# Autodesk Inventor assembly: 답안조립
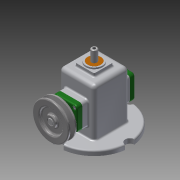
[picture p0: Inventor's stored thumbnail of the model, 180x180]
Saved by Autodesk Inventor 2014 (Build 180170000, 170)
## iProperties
Created: 2018-07
Part Number: 답안조립
Document SubType Name: Assembly
Designer: kh
Author: kh
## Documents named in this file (16)
- C:\Users\kh\Desktop\480707V1019\답안조립.iam
- C:\Users\kh\Desktop\480707V1019\본체.ipt
- C:\Users\kh\Desktop\480707V1019\V벨트풀리.ipt
- C:\Users\kh\Desktop\480707V1019\고정핀 1.2x8.ipt
- C:\Users\kh\Desktop\480707V1019\뒤커버.ipt
- C:\Users\kh\Desktop\480707V1019\링크.ipt
- C:\Users\kh\Desktop\480707V1019\멈춤나사 M3x8.ipt
- C:\Users\kh\Desktop\480707V1019\베어링 12x32x10.ipt
- C:\Users\kh\Desktop\480707V1019\볼트 M4.ipt
- C:\Users\kh\Desktop\480707V1019\부시.ipt
- C:\Users\kh\Desktop\480707V1019\슬라이드.ipt
- C:\Users\kh\Desktop\480707V1019\앞커버.ipt
- C:\Users\kh\Desktop\480707V1019\오일 실 12 25 7.ipt
- C:\Users\kh\Desktop\480707V1019\키 4x4x10.ipt
- C:\Users\kh\Desktop\480707V1019\편심축.ipt
- C:\Users\kh\Desktop\480707V1019\핀 5x18.ipt
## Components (3 placed, 3 different names)
1. V벨트풀리:1 — Insert:13, Mate:3
2. 고정핀 1.2x8:1 — Mate:5, Mate:6
3. 핀 5x18:1 — Insert:9, Mate:5, Mate:6
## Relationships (5: Mate 3, Insert 2)
- Insert:9: 핀 5x18:1
- Insert:13: V벨트풀리:1
- Mate:3: V벨트풀리:1
- Mate:5: 고정핀 1.2x8:1 ↔ 핀 5x18:1
- Mate:6: 고정핀 1.2x8:1 ↔ 핀 5x18:1
